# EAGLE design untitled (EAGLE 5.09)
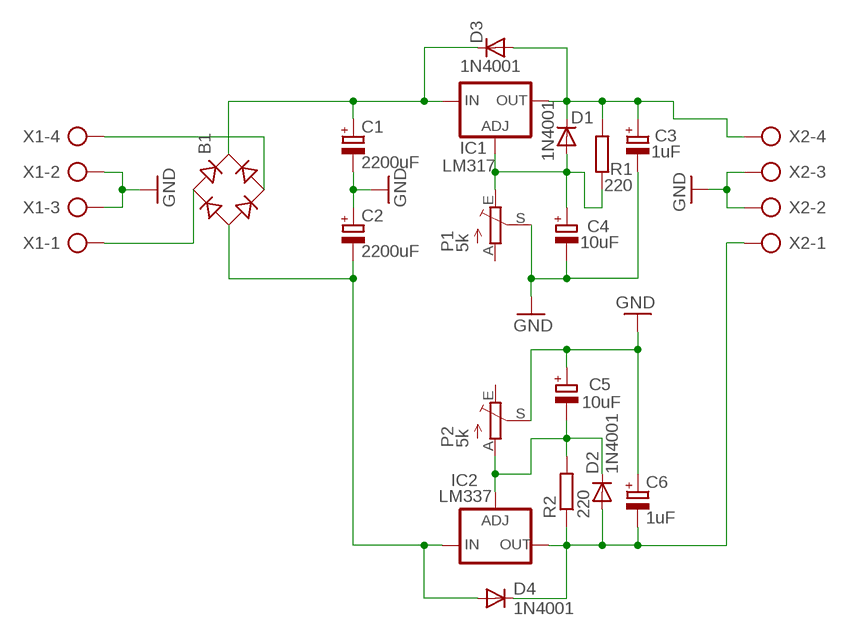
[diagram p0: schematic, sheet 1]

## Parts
B1  RB1A  [RB1A]
C1  2200uF  C-POLC7,5_16,18  [C7,5-16,18]
C2  2200uF  C-POLC7,5_16,18  [C7,5-16,18]
C3  1uF  CPOL-EUE2.5-7  [E2,5-7]
C4  10uF  CPOL-EUE2.5-6  [E2,5-6]
C5  10uF  CPOL-EUE2.5-6  [E2,5-6]
C6  1uF  CPOL-EUE2.5-7  [E2,5-7]
D1  1N4001  DIODE-DO34-7  [DO34-7]
D2  1N4001  DIODE-DO34-7  [DO34-7]
D3  1N4001  DIODE-DO34-7  [DO34-7]
D4  1N4001  DIODE-DO34-7  [DO34-7]
IC1  LM317  LM317TS  [317TS]
IC2  LM337  LM337TS  [337TS]
P1  5k  TRIM_EU-RJ9W  [RJ9W]
P2  5k  TRIM_EU-RJ9W  [RJ9W]
R1  220  R-EU_0207/10  [0207/10]
R2  220  R-EU_0207/10  [0207/10]
X1  AK500/4  [AK500/4]
X2  AK500/4  [AK500/4]

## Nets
GND: C1.- C2.+ C3.- C4.- C5.+ C6.+ P1.S P2.S X1.2 X1.3 X2.2 X2.3
N$1: C4.+ D1.A IC1.1(ADJ) P1.E R1.1
N$2: B1.- C2.- D4.A IC2.2(IN)
N$3: B1.+ C1.+ D3.C IC1.3(IN)
N$4: C3.+ D1.C D3.A IC1.2(OUT) R1.2 X2.4
N$5: B1.AC2 X1.4
N$6: B1.AC1 X1.1
N$8: C6.- D2.A D4.C IC2.3(OUT) R2.1 X2.1
N$12: C5.- D2.C IC2.1(ADJ) P2.A R2.2
Unconnected: P1.A P2.E

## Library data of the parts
B1 = rectifier:RB1A: RECTIFIER 1 A
C1 C2 = moja:C-POL
C3-C6 = resistor:CPOL-EU: POLARIZED CAPACITOR, European symbol
D1-D4 = diode:DIODE-: DIODE
IC1 = v-reg:LM317TS: VOLTAGE REGULATOR
IC2 = v-reg:LM337TS: VOLTAGE REGULATOR
P1 P2 = pot:TRIM_EU-: POTENTIOMETER
R1 R2 = resistor:R-EU_: RESISTOR, European symbol
X1 X2 = con-ptr500:AK500/4: CONNECTOR

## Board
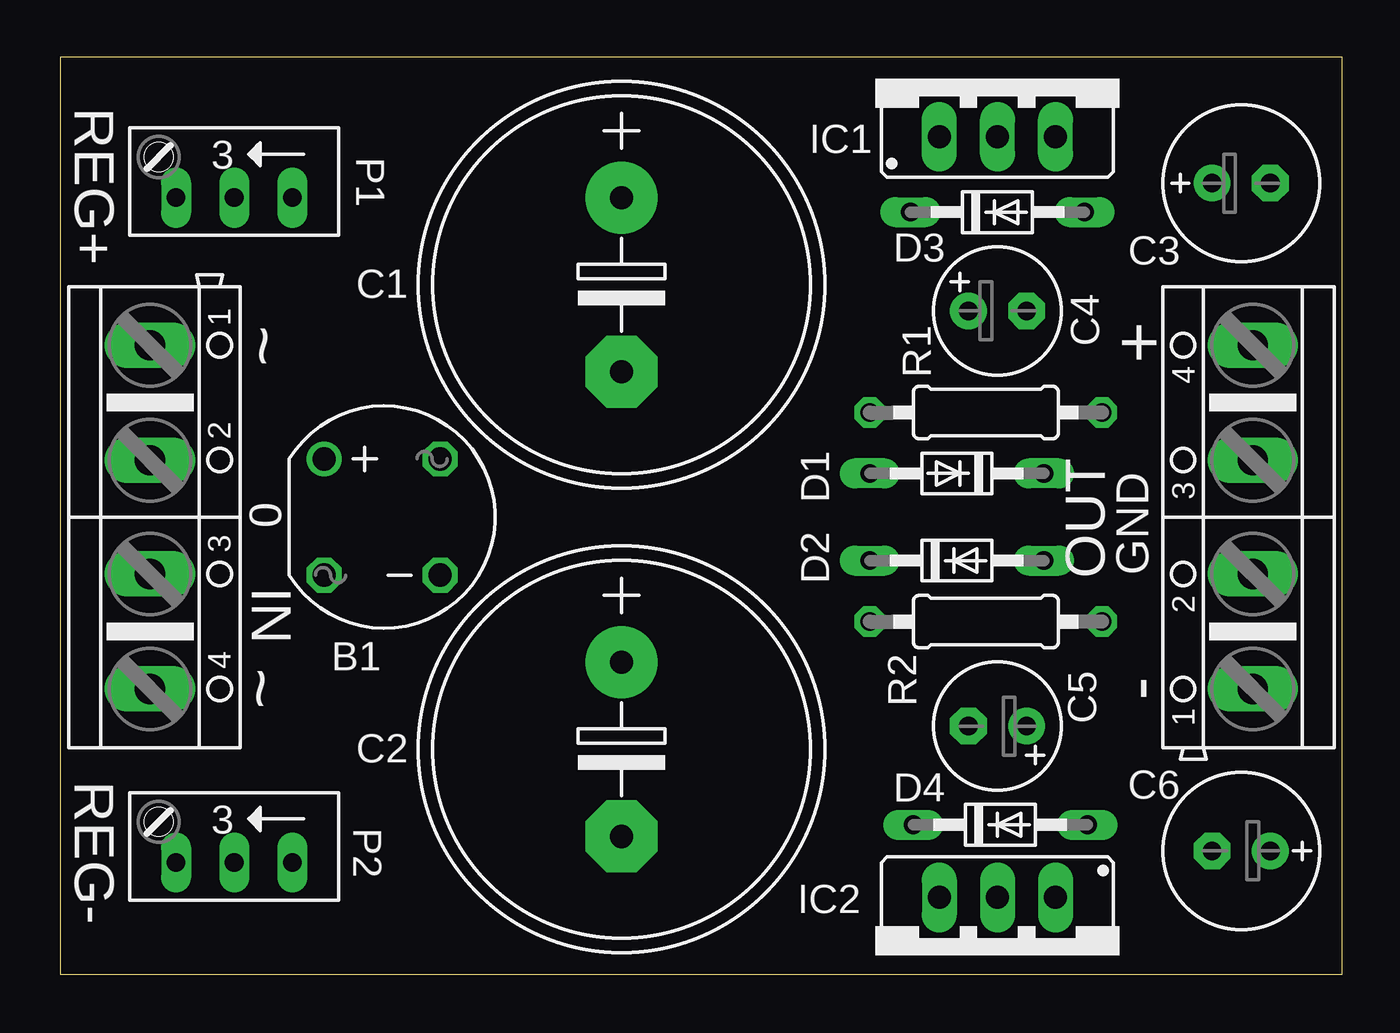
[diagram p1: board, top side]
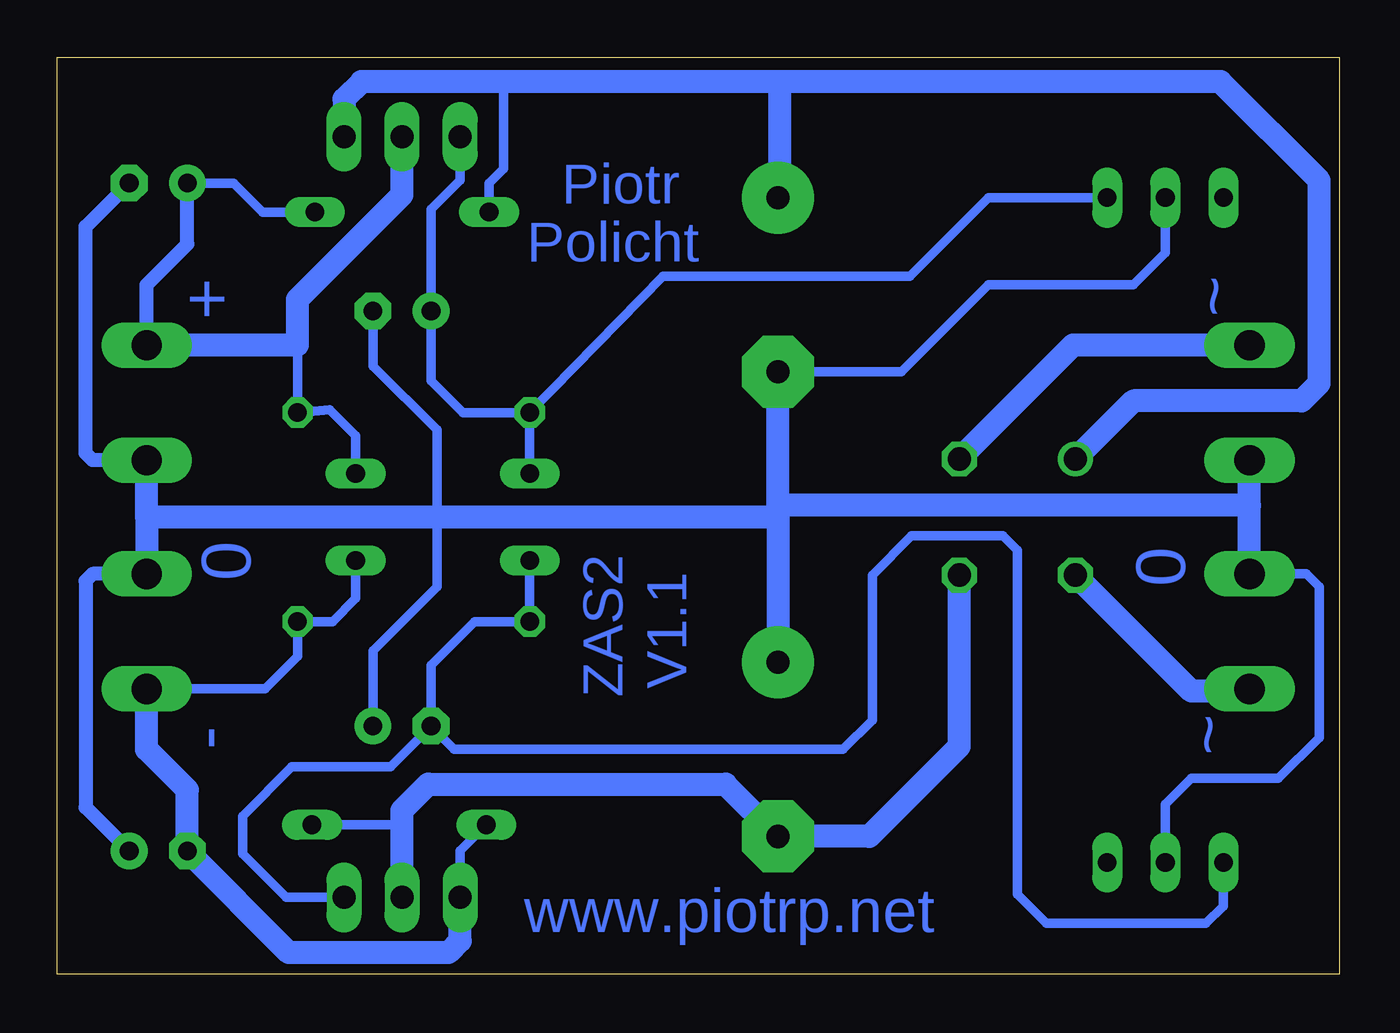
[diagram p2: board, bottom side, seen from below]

Size 56.11 x 40.12 mm. Coordinates in mm from the lower left corner, seen from the top.
Outline: 0,0 56.11,0 56.11,40.12 0,40.12 0,0
Copper layers (1*16): Top 0.035mm / dielectric 1.5mm / Bottom 0.035mm
Design rules "default": minimum track width 10mil, minimum drill 24mil, track to track 8mil, track to pad 8mil, pad to pad 8mil, via to via 8mil, smd to smd 8mil, copper to edge 40mil, drill to drill 8mil, minimum pad ring 10mil, minimum via ring 8mil, stop-mask expansion 4mil, vias tented up to drill 0mil, thermal gap 10mil

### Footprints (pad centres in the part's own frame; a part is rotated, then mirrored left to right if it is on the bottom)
RB1A = drill 1.016 round: + -2.54,2.54 | drill 1.016 octagon: - 2.54,-2.54; AC1 2.54,2.54; AC2 -2.54,-2.54
C7,5-16,18 = drill 1.016 pad 3.15 round: + -3.81,0 | drill 1.016 pad 3.15 octagon: - 3.81,0
E2,5-7 = drill 0.813 pad 1.6 round: + -1.27,0 | drill 0.813 pad 1.6 octagon: - 1.27,0
E2,5-6 = drill 0.813 pad 1.6 round: + -1.27,0 | drill 0.813 pad 1.6 octagon: - 1.27,0
DO34-7 = drill 0.813 long: A 3.81,0; C -3.81,0
317TS = drill 1.016 long: 1 -2.54,-2.54; 2 0,-2.54; 3 2.54,-2.54
337TS = drill 1.016 long: 1 -2.54,-2.54; 2 0,-2.54; 3 2.54,-2.54
RJ9W = drill 0.813 long: A 2.54,0.635; E -2.54,0.635; S 0,0.635
0207/10 = drill 0.813 octagon: 1 -5.08,0; 2 5.08,0
AK500/4 = drill 1.321 long: 1 -7.518,0; 2 -2.489,0; 3 2.489,0; 4 7.518,0

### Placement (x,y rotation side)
B1  14.1,20 0 top
C1  24.57,30.16 270 top
C2  24.57,9.84 270 top
C3  51.69,34.61 0 top
C4  41.02,29.02 0 top
C5  41.02,10.86 180 top
C6  51.69,5.4 180 top
D1  39.24,21.91 180 top
D2  39.24,18.1 0 top
D3  41.02,33.34 0 top
D4  41.15,6.54 0 top
IC1  41.02,39.18 0 top
IC2  41.02,0.83 180 top
P1  7.62,34.61 180 top
P2  7.62,5.52 180 top
R1  40.51,24.57 0 top
R2  40.51,15.43 180 top
X1  3.94,20 270 top
X2  52.2,20 90 top

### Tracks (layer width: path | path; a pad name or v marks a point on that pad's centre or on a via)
GND
  Bottom 0.406: X1.3 1.45,17.51 0.89,16.95 0.89,10.35 2.67,8.57 6.48,8.57 7.62,7.43 P2.S | P1.S 7.62,31.56 9.02,30.16 15.37,30.16 19.18,26.35 C1.- | C4.- 42.29,26.61 39.5,23.81 39.5,20 | C5.+ 42.29,14.16 39.5,16.95 39.5,19.75 39.24,20
  Bottom 0.61: C3.- 54.86,32.7 54.86,22.8 54.56,22.49 X2.3 | X2.2 54.56,17.51 54.86,17.21 54.86,7.3 C6.+
  Bottom 1.016: X1.3 3.94,20.51 | 3.94,20.51 X1.2 | 52.2,20 X2.3 | 52.2,20 X2.2 | 52.2,20 39.5,20 39.24,20 24.57,20 | 24.57,20.51 24.57,20 | 24.57,20 C2.+ | 24.57,20.51 C1.- | 3.94,20.51 24.57,20.51
N$1
  Bottom 0.406: IC1.1 38.48,34.73 39.75,33.46 C4.+ 39.75,25.97 38.35,24.57 R1.1 | R1.1 29.59,30.54 18.8,30.54 15.37,33.97 P1.E | R1.1 D1.A
N$2
  Bottom 0.406: 41.02,6.54 D4.A
  Bottom 1.016: IC2.2 41.02,6.54 41.02,7.18 39.88,8.32 26.86,8.32 C2.- 20.57,6.03 16.64,9.97 B1.-
N$3
  Bottom 0.406: D3.C 37.21,34.61 36.58,35.24 36.58,38.8 36.32,39.05
  Bottom 1.016: B1.+ 9.02,25.08 1.65,25.08 0.89,25.84 0.89,34.73 5.21,39.05 24.51,39.05 | IC1.3 43.56,38.29 42.8,39.05 36.32,39.05 24.51,39.05 | C1.+ 24.51,33.97 24.51,39.05
N$4
  Bottom 0.406: 45.59,27.52 R1.2 44.2,24.7 43.05,23.56 D1.C | D3.A 47.12,33.34 48.39,34.61 C3.+
  Bottom 0.61: C3.+ 50.42,31.94 52.2,30.16 X2.4
  Bottom 1.016: IC1.2 41.02,34.1 45.59,29.53 45.59,27.52 X2.4
N$5
  Bottom 0.406: X1.4 4.04,12.38
  Bottom 1.016: 4.04,12.38 6.48,12.38 B1.AC2
N$6
  Bottom 1.016: X1.1 11.66,27.52 B1.AC1
N$8
  Bottom 0.406: X2.1 47.02,12.48 45.59,13.91 R2.1 44.07,15.43 43.05,16.45 D2.A | D4.C 38.48,5.4 IC2.3
  Bottom 1.016: X2.1 52.2,9.84 50.42,8.06 C6.- 45.97,0.95 38.99,0.95 38.48,1.46 IC2.3
N$12
  Bottom 0.406: P2.A 5.08,2.98 5.84,2.22 12.83,2.22 14.1,3.49 14.1,18.54 14.73,19.18 18.73,19.18 20.45,17.46 20.45,11.11 21.72,9.84 38.73,9.84 C5.- | R2.2 D2.C | R2.2 35.42,15.43 | IC2.1 46.1,3.37 48.01,5.27 48.01,6.92 45.85,9.08 41.53,9.08 C5.- | C5.- 39.75,13.53 37.85,15.43 R2.2

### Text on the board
Bottom: Piotr | Policht | ~ | + | ZAS2 | V1.1 | 0 | 0 | ~ | - | www.piotrp.net
tNames: REG+ | ~ | + | 0 | OUT | GND | IN | ~ | - | REG-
